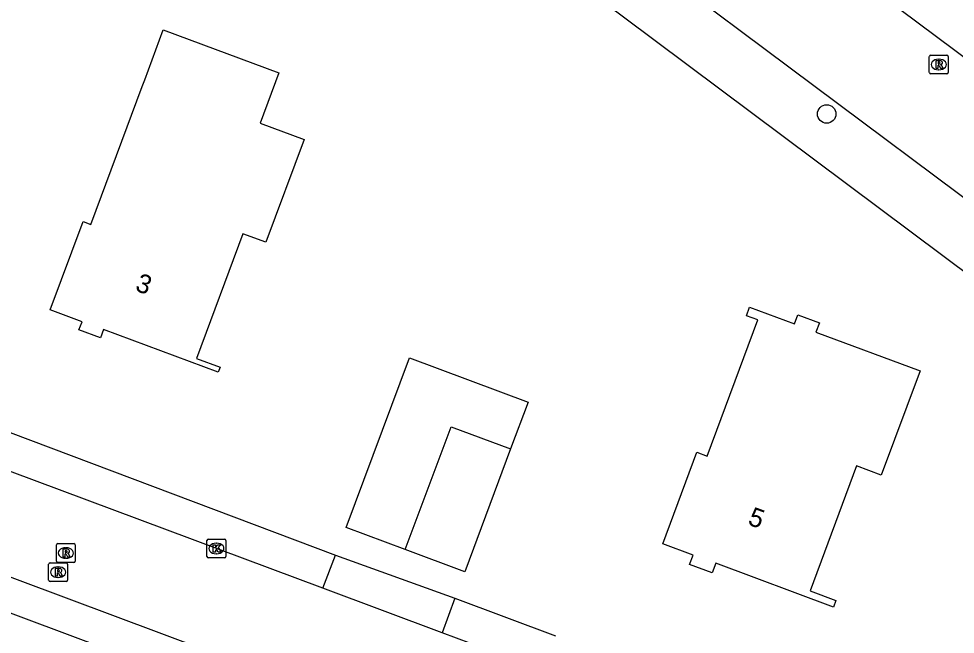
# Model space of a CAD drawing. Extents: x 163268 to 164360, y 381529 to 382285.
# Drawn here: x 163848.36 to 163897.99, y 382059.43 to 382092.02 of the extents above; entities that cross this region are included whole.
import ezdxf

# ---------------------------------------------------------------- set-up
doc = ezdxf.new("R2010")
doc.units = 0
for name, color, linetype in [('IMGEO_Boom', 7, 'Continuous'), ('IMGEO_Kolk', 7, 'Continuous'), ('IMGEO_Pand', 7, 'Continuous'), ('IMGEO_Pand_nummerreeks', 7, 'Continuous'), ('IMGEO_Rijbaan_lokaal_open', 7, 'Continuous'), ('IMGEO_Rioolput', 7, 'Continuous'), ('IMGEO_Voetpad_open', 7, 'Continuous')]:
    doc.layers.add(name, color=color, linetype=linetype)

msp = doc.modelspace()

# ---------------------------------------------------------------- linework, layer by layer
at = {"layer": 'IMGEO_Boom'}
msp.add_circle((163891.173, 382086.98), 0.489, dxfattribs=at)
at = {"layer": 'IMGEO_Kolk'}
for p, q in [((163858.335, 382063.545), (163858.335, 382064.397)), ((163858.41, 382064.471), (163859.262, 382064.471)), ((163859.336, 382064.397), (163859.336, 382063.545)), ((163858.823, 382064.251), (163858.848, 382064.251)), ((163859.262, 382063.471), (163858.41, 382063.471)), ((163858.846, 382063.691), (163858.821, 382063.691))]:
    msp.add_line(p, q, dxfattribs=at)
for points in [[(163858.335, 382063.545), (163858.335, 382064.397)], [(163858.41, 382064.471), (163859.262, 382064.471)], [(163859.336, 382064.397), (163859.336, 382063.545)], [(163858.656, 382064.171), (163858.779, 382064.171), (163858.779, 382064.02), (163858.909, 382064.171), (163859.073, 382064.171), (163858.927, 382064.02), (163859.08, 382063.771), (163858.928, 382063.771), (163858.843, 382063.935), (163858.779, 382063.868), (163858.779, 382063.771), (163858.656, 382063.771), (163858.656, 382064.171)], [(163859.262, 382063.471), (163858.41, 382063.471)]]:
    msp.add_lwpolyline(points, dxfattribs=at)
for centre, start, end in [((163858.412, 382064.395), 91.552, 178.448), ((163858.412, 382064.395), 91.552, 178.448), ((163859.26, 382064.395), 1.552, 88.448), ((163859.26, 382064.395), 1.552, 88.448), ((163858.412, 382063.547), 181.552, 268.448), ((163858.412, 382063.547), 181.552, 268.448), ((163859.26, 382063.547), 271.552, 358.448), ((163859.26, 382063.547), 271.552, 358.448)]:
    msp.add_arc(centre, 0.0765, start, end, dxfattribs=at)
for centre, major_axis, ratio, start_param, end_param in [((163858.822, 382063.971), (-0.387, 0.002), 0.722429, 4.712389, 7.853982), ((163858.847, 382063.971), (-0.39, 0.002), 0.717154, 1.570796, 4.712389)]:
    msp.add_ellipse(centre, major_axis=major_axis, ratio=ratio, start_param=start_param, end_param=end_param, dxfattribs=at)
at = {"layer": 'IMGEO_Pand'}
for points in [[(163854.905, 382088.43), (163855.04, 382088.792), (163856.023, 382091.432), (163862.142, 382089.152), (163861.152, 382086.495), (163863.488, 382085.625), (163861.462, 382080.184), (163860.243, 382080.637), (163857.787, 382074.04), (163859.036, 382073.575), (163858.936, 382073.303), (163852.855, 382075.568), (163852.687, 382075.119), (163851.552, 382075.542), (163851.715, 382075.98), (163850.034, 382076.606), (163851.777, 382081.287), (163852.188, 382081.134), (163854.905, 382088.43)], [(163884.291, 382069.068), (163884.833, 382068.867), (163887.518, 382076.078), (163886.921, 382076.3), (163887.088, 382076.749), (163889.467, 382075.863), (163889.645, 382076.343), (163890.785, 382075.919), (163890.603, 382075.43), (163896.118, 382073.376), (163894.065, 382067.863), (163892.761, 382068.349), (163890.296, 382061.731), (163891.661, 382061.223), (163891.531, 382060.874), (163885.295, 382063.197), (163885.102, 382062.679), (163883.905, 382063.125), (163884.091, 382063.622), (163882.486, 382064.22), (163884.291, 382069.068)], [(163868.846, 382063.918), (163865.717, 382065.083), (163869.061, 382074.064), (163875.349, 382071.722), (163874.426, 382069.242)], [(163868.846, 382063.918), (163871.27, 382070.418), (163874.426, 382069.242)], [(163874.426, 382069.242), (163872.005, 382062.741), (163868.846, 382063.918)]]:
    msp.add_lwpolyline(points, dxfattribs=at)
at = {"layer": 'IMGEO_Rijbaan_lokaal_open'}
for points in [[(163931.652, 382057.738), (163929.876, 382059.068), (163916.68, 382068.927), (163899.475, 382081.765), (163881.495, 382095.2), (163864.276, 382108.044), (163857.807, 382112.86), (163853.607, 382115.993)], [(163891.163, 382095.44), (163900.884, 382088.189)], [(163893.475, 382045.418), (163828.359, 382069.77)], [(163864.473, 382061.87), (163845.063, 382069.102)], [(163870.806, 382059.511), (163864.473, 382061.87)], [(163876.108, 382057.535), (163870.806, 382059.511)]]:
    msp.add_lwpolyline(points, dxfattribs=at)
at = {"layer": 'IMGEO_Rioolput'}
for p, q in [((163896.611, 382089.174), (163896.611, 382090.026)), ((163896.686, 382090.1), (163897.538, 382090.1)), ((163897.099, 382089.88), (163897.124, 382089.88)), ((163897.612, 382090.026), (163897.612, 382089.174)), ((163897.122, 382089.32), (163897.097, 382089.32)), ((163897.538, 382089.1), (163896.686, 382089.1)), ((163850.358, 382063.307), (163850.358, 382064.159)), ((163850.433, 382064.233), (163851.285, 382064.233)), ((163850.846, 382064.013), (163850.871, 382064.013)), ((163851.359, 382064.159), (163851.359, 382063.307)), ((163850.869, 382063.453), (163850.844, 382063.453)), ((163849.947, 382062.293), (163849.947, 382063.145)), ((163850.022, 382063.219), (163850.874, 382063.219)), ((163851.285, 382063.233), (163850.433, 382063.233)), ((163850.435, 382062.999), (163850.46, 382062.999)), ((163850.948, 382063.145), (163850.948, 382062.293)), ((163850.458, 382062.439), (163850.433, 382062.439)), ((163850.874, 382062.219), (163850.022, 382062.219))]:
    msp.add_line(p, q, dxfattribs=at)
for points in [[(163896.611, 382089.174), (163896.611, 382090.026)], [(163896.686, 382090.1), (163897.538, 382090.1)], [(163897.2, 382089.798), (163896.948, 382089.8), (163896.948, 382089.4)], [(163897.126, 382089.719), (163897.072, 382089.719), (163897.072, 382089.638)], [(163897.612, 382090.026), (163897.612, 382089.174)], [(163896.948, 382089.4), (163897.072, 382089.4), (163897.072, 382089.562), (163897.083, 382089.562)], [(163897.072, 382089.638), (163897.124, 382089.638)], [(163897.13, 382089.533), (163897.201, 382089.4), (163897.341, 382089.4), (163897.276, 382089.526)], [(163897.538, 382089.1), (163896.686, 382089.1)], [(163850.358, 382063.307), (163850.358, 382064.159)], [(163850.433, 382064.233), (163851.285, 382064.233)], [(163850.947, 382063.931), (163850.695, 382063.933), (163850.695, 382063.533)], [(163851.359, 382064.159), (163851.359, 382063.307)], [(163850.695, 382063.533), (163850.819, 382063.533), (163850.819, 382063.695), (163850.83, 382063.695)], [(163850.873, 382063.852), (163850.819, 382063.852), (163850.819, 382063.771)], [(163850.819, 382063.771), (163850.871, 382063.771)], [(163850.877, 382063.666), (163850.948, 382063.533), (163851.088, 382063.533), (163851.023, 382063.659)], [(163849.947, 382062.293), (163849.947, 382063.145)], [(163850.022, 382063.219), (163850.874, 382063.219)], [(163850.536, 382062.917), (163850.284, 382062.919), (163850.284, 382062.519)], [(163851.285, 382063.233), (163850.433, 382063.233)], [(163850.948, 382063.145), (163850.948, 382062.293)], [(163850.284, 382062.519), (163850.408, 382062.519), (163850.408, 382062.681), (163850.419, 382062.681)], [(163850.462, 382062.838), (163850.408, 382062.838), (163850.408, 382062.757)], [(163850.408, 382062.757), (163850.46, 382062.757)], [(163850.466, 382062.652), (163850.537, 382062.519), (163850.677, 382062.519), (163850.612, 382062.645)], [(163850.874, 382062.219), (163850.022, 382062.219)]]:
    msp.add_lwpolyline(points, dxfattribs=at)
for centre, radius, start, end in [((163896.688, 382090.024), 0.0765, 91.552, 178.448), ((163896.688, 382090.024), 0.0765, 91.552, 178.448), ((163897.132, 382089.623), 0.0964, 77.0061, 93.1865), ((163897.146, 382089.68), 0.0378, 276.6634, 79.6772), ((163897.199, 382089.688), 0.109, 350.3612, 89.416), ((163897.536, 382090.024), 0.0765, 1.552, 88.448), ((163897.536, 382090.024), 0.0765, 1.552, 88.448), ((163897.082, 382089.509), 0.0533, 26.0293, 88.6989), ((163897.108, 382089.827), 0.19, 274.7715, 282.9687), ((163897.197, 382089.688), 0.112, 277.5842, 350.9817), ((163897.181, 382089.473), 0.108, 29.5134, 73.7905), ((163896.688, 382089.176), 0.0765, 181.552, 268.448), ((163896.688, 382089.176), 0.0765, 181.552, 268.448), ((163897.536, 382089.176), 0.0765, 271.552, 358.448), ((163897.536, 382089.176), 0.0765, 271.552, 358.448), ((163850.435, 382064.157), 0.0765, 91.552, 178.448), ((163850.435, 382064.157), 0.0765, 91.552, 178.448), ((163850.946, 382063.821), 0.109, 350.3612, 89.416), ((163851.283, 382064.157), 0.0765, 1.552, 88.448), ((163851.283, 382064.157), 0.0765, 1.552, 88.448), ((163850.829, 382063.642), 0.0533, 26.0293, 88.6989), ((163850.855, 382063.96), 0.19, 274.7715, 282.9687), ((163850.879, 382063.756), 0.0964, 77.0061, 93.1865), ((163850.893, 382063.813), 0.0378, 276.6634, 79.6772), ((163850.944, 382063.821), 0.112, 277.5842, 350.9817), ((163850.928, 382063.606), 0.108, 29.5134, 73.7905), ((163850.024, 382063.143), 0.0765, 91.552, 178.448), ((163850.024, 382063.143), 0.0765, 91.552, 178.448), ((163850.435, 382063.309), 0.0765, 181.552, 268.448), ((163850.435, 382063.309), 0.0765, 181.552, 268.448), ((163850.535, 382062.807), 0.109, 350.3612, 89.416), ((163850.872, 382063.143), 0.0765, 1.552, 88.448), ((163850.872, 382063.143), 0.0765, 1.552, 88.448), ((163851.283, 382063.309), 0.0765, 271.552, 358.448), ((163851.283, 382063.309), 0.0765, 271.552, 358.448), ((163850.418, 382062.628), 0.0533, 26.0293, 88.6989), ((163850.444, 382062.946), 0.19, 274.7715, 282.9687), ((163850.468, 382062.742), 0.0964, 77.0061, 93.1865), ((163850.482, 382062.799), 0.0378, 276.6634, 79.6772), ((163850.533, 382062.807), 0.112, 277.5842, 350.9817), ((163850.517, 382062.592), 0.108, 29.5134, 73.7905), ((163850.024, 382062.295), 0.0765, 181.552, 268.448), ((163850.024, 382062.295), 0.0765, 181.552, 268.448), ((163850.872, 382062.295), 0.0765, 271.552, 358.448), ((163850.872, 382062.295), 0.0765, 271.552, 358.448)]:
    msp.add_arc(centre, radius, start, end, dxfattribs=at)
for centre, major_axis, ratio, start_param, end_param in [((163897.098, 382089.6), (-0.387, 0.002), 0.722429, 4.712389, 7.853982), ((163897.123, 382089.6), (-0.39, 0.002), 0.717154, 1.570796, 4.712389), ((163850.845, 382063.733), (-0.387, 0.002), 0.722429, 4.712389, 7.853982), ((163850.87, 382063.733), (-0.39, 0.002), 0.717154, 1.570796, 4.712389), ((163850.434, 382062.719), (-0.387, 0.002), 0.722429, 4.712389, 7.853982), ((163850.459, 382062.719), (-0.39, 0.002), 0.717154, 1.570796, 4.712389)]:
    msp.add_ellipse(centre, major_axis=major_axis, ratio=ratio, start_param=start_param, end_param=end_param, dxfattribs=at)
at = {"layer": 'IMGEO_Voetpad_open'}
for points in [[(163844.84, 382118.673), (163876.191, 382095.274), (163880.403, 382092.13), (163921.027, 382061.786)], [(163845.732, 382070.921), (163865.151, 382063.623)], [(163892.832, 382043.759), (163827.735, 382068.081)], [(163864.473, 382061.87), (163865.151, 382063.623)], [(163865.151, 382063.623), (163871.466, 382061.345)], [(163871.466, 382061.345), (163870.806, 382059.511)], [(163871.466, 382061.345), (163876.809, 382059.354)]]:
    msp.add_lwpolyline(points, dxfattribs=at)

# ---------------------------------------------------------------- texts
at = {"layer": 'IMGEO_Pand_nummerreeks'}
for s, rotation, p in [('3', 339.6543, (163854.479, 382077.645)), ('5', 339.7223, (163886.941, 382065.26))]:
    msp.add_text(s, height=1, rotation=rotation, dxfattribs=at).set_placement(p)

doc.saveas('drawing.dxf')
